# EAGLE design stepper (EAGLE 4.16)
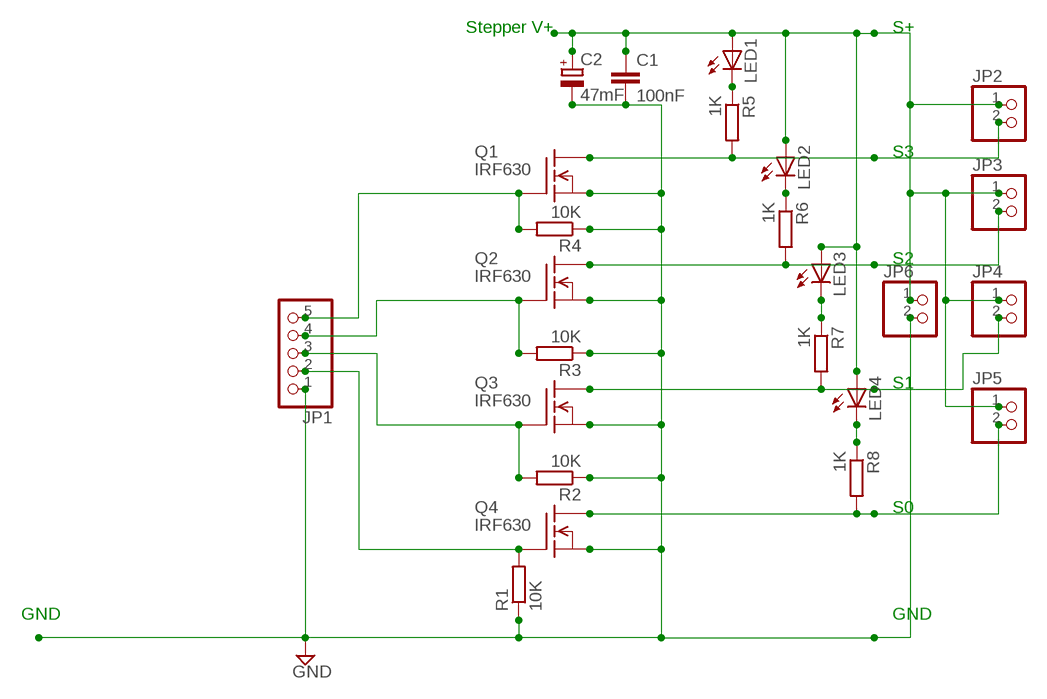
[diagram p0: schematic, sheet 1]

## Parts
C1  100nF  C-EU050-035X075  [C050-035X075]
C2  47mF  CPOL-EUE30-12AXIAL  [E30-12]
JP1  PINHD-1X5  [1X05]
JP2  PINHD-1X2  [1X02]
JP3  PINHD-1X2  [1X02]
JP4  PINHD-1X2  [1X02]
JP5  PINHD-1X2  [1X02]
JP6  PINHD-1X2  [1X02]
LED1  LED3MM  [LED3MM]
LED2  LED3MM  [LED3MM]
LED3  LED3MM  [LED3MM]
LED4  LED3MM  [LED3MM]
Q1  IRF630  IRF620  [TO220]
Q2  IRF630  IRF620  [TO220]
Q3  IRF630  IRF620  [TO220]
Q4  IRF630  IRF620  [TO220]
R1  10K  R-EU_0411/12  [0411/12]
R2  10K  R-EU_0411/12  [0411/12]
R3  10K  R-EU_0411/12  [0411/12]
R4  10K  R-EU_0411/12  [0411/12]
R5  1K  R-EU_0411/12  [0411/12]
R6  1K  R-EU_0411/12  [0411/12]
R7  1K  R-EU_0411/12  [0411/12]
R8  1K  R-EU_0411/12  [0411/12]

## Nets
GND: C1.2 C2.- JP1.1 JP6.2 Q1.3(S) Q2.3(S) Q3.3(S) Q4.3(S) R1.1 R2.1 R3.1 R4.1
N$2: JP1.5 Q1.1(G) R4.2
N$3: JP5.2 Q4.2(D) R8.2
N$5: JP1.4 Q2.1(G) R3.2
N$6: JP1.3 Q3.1(G) R2.2
N$7: C1.1 C2.+ JP2.1 JP3.1 JP4.1 JP5.1 JP6.1 LED1.A LED2.A LED3.A LED4.A
N$8: JP3.2 Q2.2(D) R6.2
N$9: JP1.2 Q4.1(G) R1.2
N$11: JP2.2 Q1.2(D) R5.2
N$12: JP4.2 Q3.2(D) R7.2
N$20: LED4.K(C) R8.1
N$22: LED2.K(C) R6.1
N$23: LED1.K(C) R5.1
N$25: LED3.K(C) R7.1

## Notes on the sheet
- Stepper V+ | S+
- S3
- S2
- S1
- S0
- GND | GND

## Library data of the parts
C1 = rcl:C-EU: CAPACITOR, European symbol
C2 = rcl:CPOL-EU: POLARIZED CAPACITOR, European symbol
JP1 = pinhead:PINHD-1X5: PIN HEADER
JP2-JP6 = pinhead:PINHD-1X2: PIN HEADER
LED1-LED4 = led:LED: LED
Q1-Q4 = transistor-fet:IRF620: N-Channel Enhancement MOSFET (HEXFET); 200V; 5,2A; 0,8Ohm
R1-R8 = rcl:R-EU_: RESISTOR, European symbol

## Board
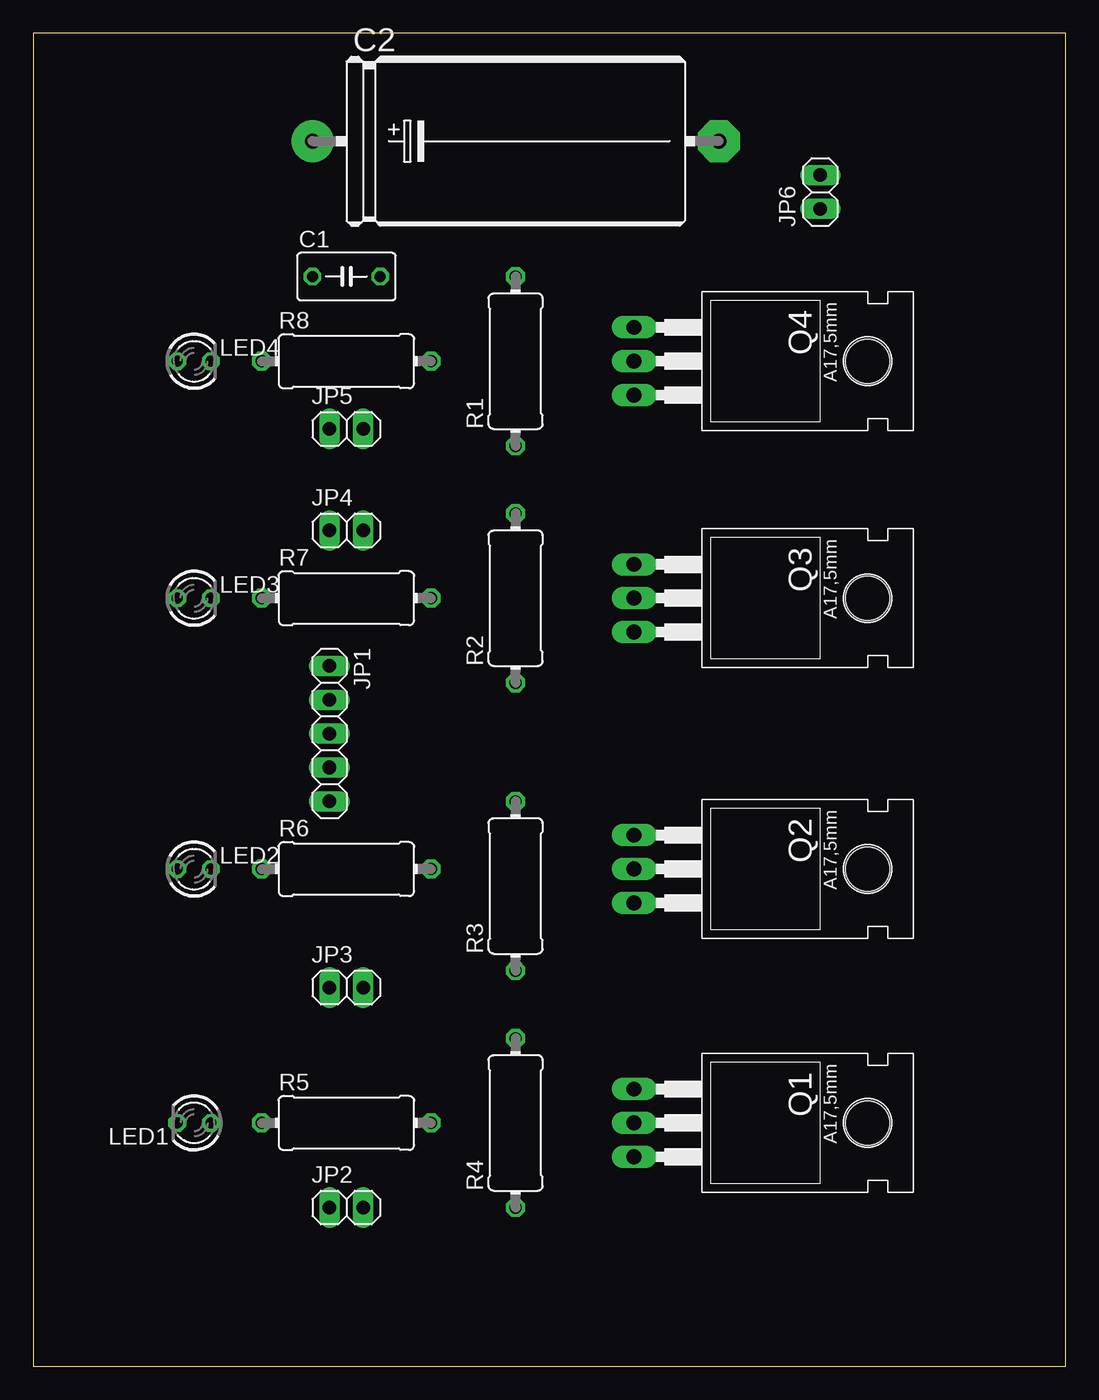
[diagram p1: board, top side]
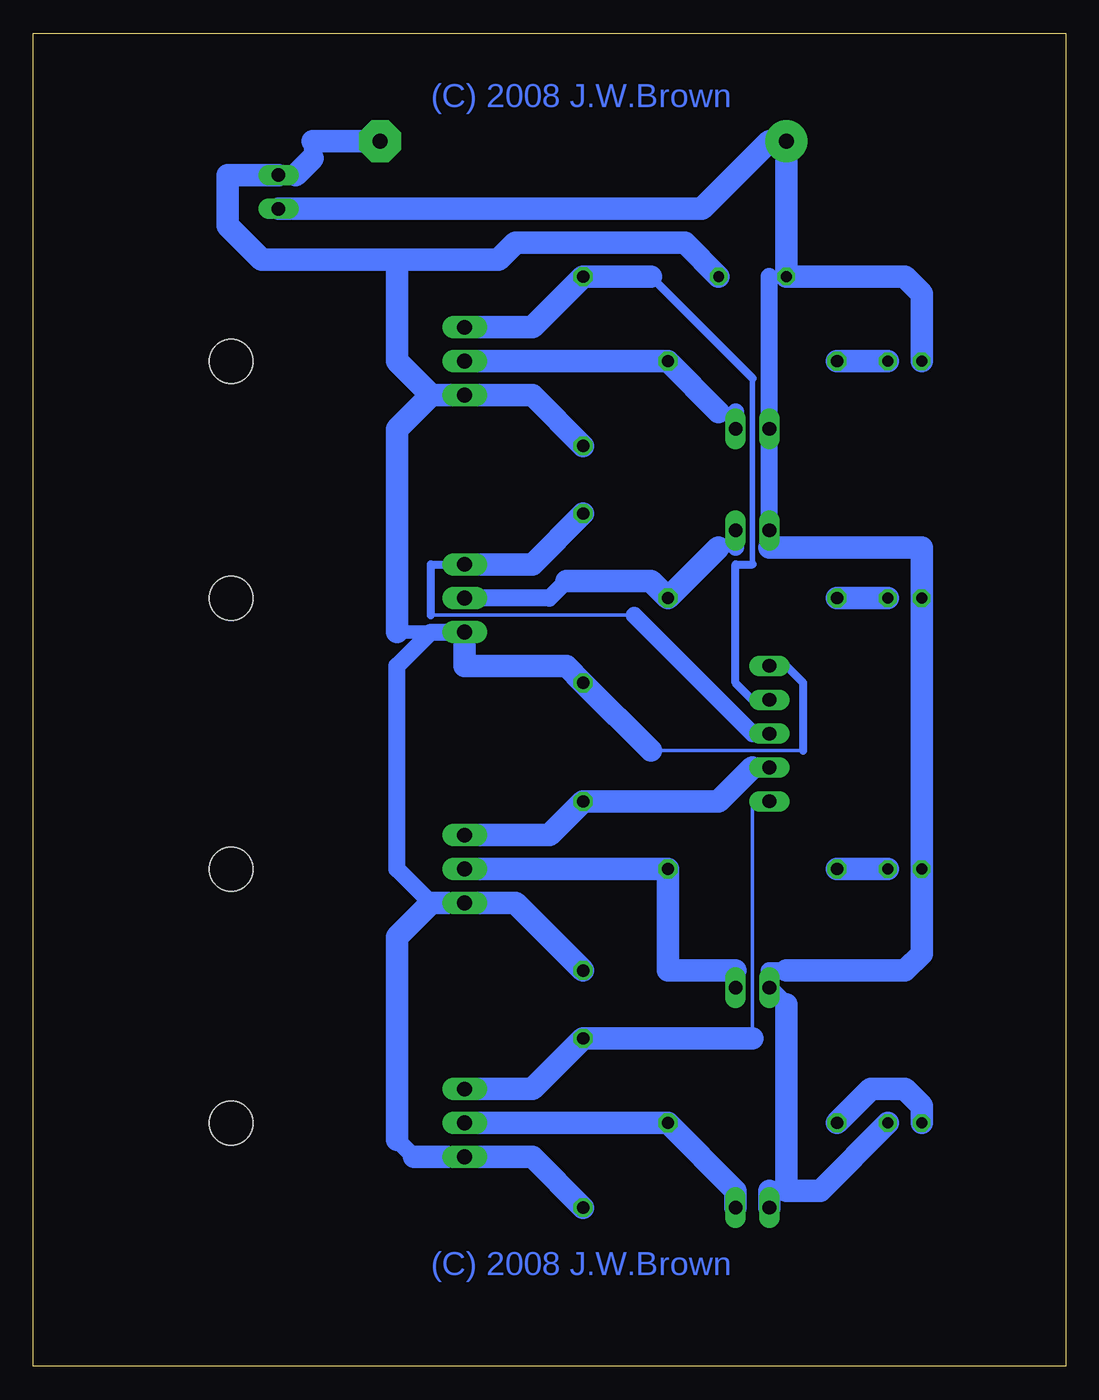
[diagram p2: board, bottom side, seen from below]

Size 77.45 x 100 mm. Coordinates in mm from the lower left corner, seen from the top.
Outline: 0,0 77.45,0 77.45,100 0,100 0,0
Copper layers (1*16): Top 0.035mm / dielectric 1.5mm / Bottom 0.035mm
Design rules "default": minimum track width 10mil, minimum drill 24mil, track to track 8mil, track to pad 8mil, pad to pad 8mil, via to via 8mil, smd to smd 8mil, copper to edge 40mil, drill to drill 8mil, minimum pad ring 10mil, minimum via ring 8mil, stop-mask expansion 4mil, vias tented up to drill 0mil, thermal gap 10mil

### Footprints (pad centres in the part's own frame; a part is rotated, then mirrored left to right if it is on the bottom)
C050-035X075 = drill 0.813 octagon: 1 -2.54,0; 2 2.54,0
E30-12 = drill 1.118 pad 3.15 round: + -15.24,0 | drill 1.118 pad 3.15 octagon: - 15.24,0
1X05 = drill 1.016 long: 1 -5.08,0; 2 -2.54,0; 3 0,0; 4 2.54,0; 5 5.08,0
1X02 = drill 1.016 long: 1 -1.27,0; 2 1.27,0
LED3MM = drill 0.813 octagon: A -1.27,0; K 1.27,0
TO220 = drill 1.118 long: 1 -2.54,-6.35; 2 0,-6.35; 3 2.54,-6.35 | hole 3.302: 0,11.176
0411/12 = drill 0.914 octagon: 1 -6.35,0; 2 6.35,0

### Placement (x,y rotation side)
C1  23.49,81.75 0 top
C2  36.19,91.91 0 top
JP1  22.22,47.46 270 top
JP2  23.49,11.9 0 top
JP3  23.49,28.41 0 top
JP4  23.49,62.7 0 top
JP5  23.49,70.32 0 top
JP6  59.05,88.1 90 top
LED1  12.06,18.25 180 top
LED2  12.06,37.3 0 top
LED3  12.06,57.62 0 top
LED4  12.06,75.4 0 top
Q1  51.43,18.25 270 top
Q2  51.43,37.3 270 top
Q3  51.43,57.62 270 top
Q4  51.43,75.4 270 top
R1  36.19,75.4 90 top
R2  36.19,57.62 90 top
R3  36.19,36.03 90 top
R4  36.19,18.25 90 top
R5  23.49,18.25 0 top
R6  23.49,37.3 0 top
R7  23.49,57.62 0 top
R8  23.49,75.4 0 top

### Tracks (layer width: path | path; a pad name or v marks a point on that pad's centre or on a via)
GND
  Bottom 0.254: Q1.3 46.35,15.71 | 19.68,46.19 31.11,46.19 | 20.95,52.54 JP1.1 | 57.78,89.37 JP6.2 60.32,89.37 | 46.35,34.76 Q2.3
  Bottom 0.61: 20.95,52.54 19.68,51.27 19.68,46.19
  Bottom 1.016: 47.62,55.08 50.16,55.08
  Bottom 1.27: Q3.3 47.62,55.08 50.16,52.54 50.16,37.3 47.62,34.76 | 48.89,15.71 50.16,16.98 | 56.51,90.64 56.51,91.91
  Bottom 1.676: R4.1 40,15.71 Q1.3 | R3.1 41.27,34.76 Q2.3 | 47.62,72.86 Q4.3 40,72.86 R1.1 | 46.35,15.71 48.89,15.71 | 50.16,16.98 50.16,32.22 47.62,34.76 46.35,34.76 | 50.16,55.08 50.16,70.32 47.62,72.86 | 50.16,83.02 50.16,75.4 47.62,72.86 | 50.16,83.02 60.32,83.02 62.86,85.56 62.86,89.37 JP6.2 | 57.78,89.37 56.51,90.64 | 56.51,91.91 C2.- | C1.2 28.57,84.29 41.27,84.29 42.54,83.02 50.16,83.02 | 31.11,46.19 R2.1 37.46,52.54 45.08,52.54 Q3.3
N$2
  Bottom 0.254: 23.49,24.6 23.49,42.38 JP1.5
  Bottom 1.676: Q1.1 40,20.79 R4.2 23.49,24.6
N$3
  Bottom 0.254: 24.76,71.59 26.03,71.59
  Bottom 1.27: JP5.2 24.76,71.59
  Bottom 1.676: 26.03,71.59 R8.2 Q4.2
N$5
  Bottom 1.27: JP1.4 23.49,44.92
  Bottom 1.676: Q2.1 38.73,39.84 R3.2 26.03,42.38 23.49,44.92
N$6
  Bottom 0.254: 32.38,56.35 47.62,56.35 | JP1.3 23.49,47.46
  Bottom 0.61: 47.62,56.35 47.62,60.16 Q3.1
  Bottom 1.27: 23.49,47.46 32.38,56.35
  Bottom 1.676: R2.2 40,60.16 Q3.1
N$7
  Bottom 0.254: JP3.1 22.22,29.68 | 22.22,61.43 JP4.1 | JP6.1 57.78,86.83 | 22.22,81.75 C1.1
  Bottom 1.27: 20.95,13.17 22.22,13.17 | 22.22,29.68 20.95,29.68 18.41,29.68 | JP4.1 JP5.1 22.22,81.75 | C2.+ 22.22,91.91 | 20.95,27.14 JP3.1
  Bottom 1.676: LED1.A 18.41,13.17 20.95,13.17 20.95,27.14 | 22.22,13.17 JP2.1 | C2.+ C1.1 17.14,81.75 12.06,81.75 10.79,80.48 LED4.A | 22.22,91.91 27.3,86.83 JP6.1 | 20.95,29.68 12.06,29.68 10.79,30.95 LED2.A LED3.A 10.79,61.43 22.22,61.43
N$8
  Bottom 0.254: JP3.2 24.76,29.68
  Bottom 1.676: 24.76,29.68 29.84,29.68 R6.2 Q2.2
N$9
  Bottom 0.406: 23.49,60.16 23.49,74.13
  Bottom 0.61: 23.49,60.16 24.76,60.16 24.76,51.27 23.49,50 JP1.2 | 23.49,74.13 31.11,81.75
  Bottom 1.676: Q4.1 40,77.94 R1.2 31.11,81.75
N$11
  Bottom 1.676: JP2.2 24.76,13.17 R5.2 Q1.2
N$12
  Bottom 0.254: 24.76,61.43 26.03,61.43
  Bottom 1.27: JP4.2 24.76,61.43 | 37.46,58.89 38.73,57.62 Q3.2
  Bottom 1.676: 26.03,61.43 R7.2 31.11,58.89 37.46,58.89
N$20
  Bottom 1.676: LED4.K R8.1
N$22
  Bottom 1.676: LED2.K R6.1
N$23
  Bottom 1.676: R5.1 14.6,20.79 12.06,20.79 10.79,19.52 LED1.K
N$25
  Bottom 1.676: LED3.K R7.1

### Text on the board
Bottom: (C) 2008 J.W.Brown | (C) 2008 J.W.Brown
